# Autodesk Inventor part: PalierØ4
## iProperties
Created: 2011-07
Part Number: PalierØ4
Document SubType Name: Modeling
Designer: domi
Density: 1 g/cm^3
Author: domi
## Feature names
1. Pallier [Extrusion]
